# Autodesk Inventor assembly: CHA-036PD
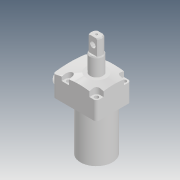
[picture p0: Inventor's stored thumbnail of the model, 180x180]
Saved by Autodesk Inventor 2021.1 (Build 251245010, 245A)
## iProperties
Created: 2018-12
Part Number: CHA-036PD
Description: STEP AP214
Document SubType Name: Assembly
Designer: user
Title: CHA-036PD.STEP
Revision Number: ÈÎºÎ
Sending System: SolidWorks 2016
Preprocessor: SwSTEP 2.0
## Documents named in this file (4)
- D:\Vault_2016\Projekty\Clamptek\Hydraulic\CHA-P\Inventor\CHA-036PD\CHA-036PD.iam
- D:\Vault_2016\Projekty\Clamptek\Hydraulic\CHA-P\Inventor\CHA-036PD\CHA-036P(BT).ipt
- D:\Vault_2016\Projekty\Clamptek\Hydraulic\CHA-P\Inventor\CHA-036PD\¶ÂÍ·G8-1.ipt
- D:\Vault_2016\Projekty\Clamptek\Hydraulic\CHA-P\Inventor\CHA-036PD\CHA-036PD(HSG).ipt
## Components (4 placed, 4 different names)
1. CHA-036P(BT)_1
2. ¶ÂÍ·G8-1_2
3. CHA-036PD(HSG)_3
4. ¶ÂÍ·G8-1_4
